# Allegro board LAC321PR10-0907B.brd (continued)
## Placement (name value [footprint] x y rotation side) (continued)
PQ600  AON7934_DFN3X3A-8-10  [AON7934_DFN3X3A8-10]  156.91 125.89 90 top
PQ601  AON7934_DFN3X3A-8-10  [AON7934_DFN3X3A8-10]  162.37 108.98 180 top
PQ800  AON7934_DFN3X3A-8-10  [AON7934_DFN3X3A8-10]  83.33 108 0 top
PQ900  AON7934_DFN3X3A-8-10  [AON7934_DFN3X3A8-10]  82.95 119.18 0 top
PQ1000  AON7934_DFN3X3A-8-10  [AON7934_DFN3X3A8-10]  77.41 100.35 180 top
PR102  100K_0402_1%  [R_0402]  45.21 109.29 90 top
PR103  0_0402_5%  [R_0402]  41.28 127.24 0 top
PR104  1M_0402_5%  [R_0402]  45.21 107.53 90 top
PR105  100K_0402_1%  [R_0402]  49.14 125.44 180 top
PR106  100K_0402_1%  [R_0402]  46.36 124.44 0 top
PR107  100K_0402_1%  [R_0402]  41.32 118.7 90 top
PR108  100K_0402_1%  [R_0402]  51.52 112.49 270 top
PR109  0_0201_1%  [R_0201]  44.75 124.8 0 top
PR110  0_0201_1%  [R_0201]  46.72 129.13 90 top
PR111  100K_0402_1%  [R_0402]  48.26 128.06 90 top
PR112  0_0201_1%  [R_0201]  43.96 128.3 180 top
PR113  0_0201_1%  [R_0201]  46.72 130.88 270 top
PR115  221K_0402_1%  [R_0402]  47.57 139.09 270 top
PR116  100K_0402_1%  [R_0402]  50.68 109.52 90 top
PR117  19.1K_0402_1%  [R_0402]  41.27 140.5 0 top
PR118  0_0402_5%  [R_0402]  42.21 123.35 270 top
PR119  1M_0402_5%  [R_0402]  50.67 107.78 90 top
PR120  100K_0402_1%  [R_0402]  162.36 96.6 270 top
PR121  100_0402_1%  [R_0402]  158.86 95.82 90 top
PR122  100_0402_1%  [R_0402]  159.75 95.82 90 top
PR123  100_0402_1%  [R_0402]  160.59 96.58 0 top
PR124  25.5K_0402_1%  [R_0402]  48.23 126.33 0 top
PR125  25.5K_0402_1%  [R_0402]  49.16 128.99 270 top
PR126  221K_0402_1%  [R_0402]  47.4 135.3 90 top
PR127  100K_0402_1%  [R_0402]  47.28 125.31 180 top
PR128  1.8M_0402_1%  [R_0402]  46.67 137.32 0 top
PR129  100K_0402_1%  [R_0402]  41.33 122.44 90 top
PR130  1.8M_0402_1%  [R_0402]  42.14 135.24 90 top
PR131  0_0402_5%  [R_0402]  42.21 121.36 270 top
PR132  100K_0402_1%  [R_0402]  41.32 120.44 90 top
PR133  100K_0402_1%  [R_0402]  47.68 140.55 180 top
PR134  100K_0402_1%  [R_0402]  44.05 140.54 180 top
PR135  0_0402_5%  [R_0402]  41.31 128.18 0 top
PR136  200K_0402_1%  [R_0402]  42.17 137.84 90 top
PR137  100K_0402_1%  [R_0402]  44.05 133.37 270 top
PR138  100K_0402_1%  [R_0402]  45.83 132.46 90 top
PR139  1M_0402_5%  [R_0402]  42.2 117.85 270 top
PR140  200K_0402_1%  [R_0402]  41.28 134.35 0 top
PR141  1M_0402_5%  [R_0402]  51.52 114.22 270 top
PR142  19.1K_0402_1%  [R_0402]  42.18 132.51 90 top
PR143  0_0402_5%  [R_0402]  48.16 129.88 0 top
PR144  0_0402_5%  [R_0402]  45.88 131.61 0 top
PR145  1K_0402_1%  [R_0402]  51.57 109.52 90 top
PR146  0_0402_5%  [R_0402]  41.27 125.47 0 top
PR147  0_0402_5%  [R_0402]  43.99 131.54 0 top
PR148  0_0402_5%  [R_0402]  41.28 126.35 0 top
PR149  100K_0402_1%  [R_0402]  44.52 85.97 90 top
PR150  0_0402_5%  [R_0402]  26.41 91.24 0 top
PR151  2K_0402_5%  [R_0402]  41.79 85.97 90 top
PR152  0_0402_5%  [R_0402]  26.51 86.67 180 top
PR153  100K_0402_1%  [R_0402]  39.39 91.82 180 top
PR155  100K_0402_1%  [R_0402]  34.18 71.56 90 top
PR156  0_0201_1%  [R_0201]  46.93 139.8 0 top
PR157  100K_0402_1%  [R_0402]  42.2 91.96 90 top
PR158  100K_0402_1%  [R_0402]  43.08 92.86 270 top
PR159  0_0402_5%  [R_0402]  41.07 96.79 90 top
PR160  0_0402_5%  [R_0402]  40.42 92.87 270 top
PR161  0_0402_5%  [R_0402]  160.59 95.69 0 top
PR162  100K_0402_1%  [R_0402]  41.31 92.87 270 top
PR165  0_0805_5%  [R_0805]  83.42 87.84 90 top
PR166  0_0805_5%  [R_0805]  81.69 87.84 90 top
PR167  0_0805_5%  [R_0805]  79.98 87.84 90 top
PR200  1M_0402_5%  [R_0402]  51.3 135.81 180 top
PR201  100K_0402_1%  [R_0402]  66.27 140.98 90 top
PR202  100K_0402_1%  [R_0402]  53.88 148.68 270 top
PR203  100K_0402_1%  [R_0402]  66.2 137.07 0 top
PR204  1M_0402_5%  [R_0402]  49.54 135.81 180 top
PR205  1M_0402_5%  [R_0402]  64.37 141.85 0 top
PR206  1M_0402_5%  [R_0402]  76.38 119.79 180 top
PR207  100K_0402_1%  [R_0402]  61.73 139.63 90 top
PR208  100K_0402_1%  [R_0402]  60.7 138.59 180 top
PR209  1.8M_0402_1%  [R_0402]  80.12 129.19 270 top
PR210  100K_0402_1%  [R_0402]  61.32 148.57 0 top
PR211  115K_0402_1%  [R_0402]  74.5 128.38 90 top
PR212  430K_0402_5%  [R_0402]  73.62 128.38 90 top
PR213  249K_0402_1%  [R_0402]  78.23 129.18 180 top
PR214  0_0402_5%  [R_0402]  62.22 147.7 270 top
PR215  1M_0402_5%  [R_0402]  61.58 137.88 90 top
PR216  1M_0402_5%  [R_0402]  60.68 136.19 90 top
PR217  422K_0402_1%  [R_0402]  76.43 128.32 180 top
PR218  165K_0402_1%  [R_0402]  65.31 120.33 0 top
PR219  100K_0402_1%  [R_0402]  66.22 119.44 180 top
PR220  78.7K_0402_1%  [R_0402]  68.15 129.33 180 top
PR221  15.4K_0402_1%  [R_0402]  67.37 128.23 0 top
PR222  49.9K_0402_1%  [R_0402]  68.28 127.35 180 top
PR223  2K_0402_5%  [R_0402]  55.92 148.69 270 top
PR224  100K_0402_1%  [R_0402]  53 147.76 90 top
PR225  100K_0402_1%  [R_0402]  72.57 122.97 180 top
PR226  0_0402_5%  [R_0402]  70.75 122.97 180 top
PR227  100K_0402_1%  [R_0402]  72.88 124.04 90 top
PR228  0_0402_5%  [R_0402]  77.63 123.6 0 top
PR229  2M_0402_5%  [R_0402]  66.34 123.07 0 top
PR230  2M_0402_5%  [R_0402]  70.14 128.02 0 top
PR231  0_0402_5%  [R_0402]  54.81 148.67 270 top
PR232  0_0402_5%  [R_0402]  56.81 148.69 270 top
PR233  0_0201_1%  [R_0201]  50.89 143.34 90 top
PR234  0_0201_1%  [R_0201]  49.74 143.34 90 top
PR235  0_0201_1%  [R_0201]  51.64 143.34 90 top
PR236  0_0201_1%  [R_0201]  50.33 143.34 90 top
PR237  560K_0402_5%  [R_0402]  59.21 146.24 0 top
PR238  0_0201_1%  [R_0201]  61.36 143.81 270 top
PR239  0_0201_1%  [R_0201]  69.55 129.32 180 top
PR240  0_0402_5%  [R_0402]  72.12 128.15 90 top
PR241  560K_0402_5%  [R_0402]  74.33 122.77 90 top
PR242  0_0402_5%  [R_0402]  70.31 129.07 0 top
PR243  0_0402_5%  [R_0402]  65.31 123.24 90 top
PR244  100K_0402_1%  [R_0402]  60.85 140.55 270 top
PR245  560K_0402_5%  [R_0402]  74.48 120.05 180 top
PR246  100K_0402_1%  [R_0402]  61.63 134.24 270 top
PR247  560K_0402_5%  [R_0402]  62.28 143.6 270 top
PR248  0_0402_5%  [R_0402]  73.64 121.9 270 top
PR249  100K_0402_1%  [R_0402]  75.47 120.68 0 top
PR250  0_0402_5%  [R_0402]  173.16 109.32 0 top
PR251  20K_0402_1%  [R_0402]  59.98 142.25 180 top
PR252  100K_0201_1%  [R_0201]  89.66 93.57 90 top
PR253  100K_0201_1%  [R_0201]  90.23 93.57 90 top
PR254  165K_0402_1%  [R_0402]  65.42 117.64 90 top
PR255  100K_0402_1%  [R_0402]  50.74 141.61 180 top
PR256  78.7K_0402_1%  [R_0402]  65.31 129.32 0 top
PR257  0_0402_5%  [R_0402]  94.62 94.46 90 top
PR258  100K_0402_1%  [R_0402]  93.71 96.22 90 top
PR259  0_0402_5%  [R_0402]  68.35 119.13 180 top
PR300  1M_0402_5%  [R_0402]  168.24 109.32 0 top
PR301  1M_0402_5%  [R_0402]  168.74 108.36 180 top
PR302  100K_0402_5%  [R_0402]  171.91 107.6 180 top
PR303  100K_0402_5%  [R_0402]  171.91 106.71 180 top
PR304  820K_0402_1%  [R_0402]  169.63 104.94 180 top
PR305  0_0201_1%  [R_0201]  166.63 109.14 90 top
PR306  0_0201_1%  [R_0201]  167.2 109.72 270 top
PR307  0_0201_1%  [R_0201]  170.02 108.24 180 top
PR400  0.01_1206_1%  [R_1206_4P-D]  43.07 117.86 0 top
PR401  0_0402_5%  [R_0402]  57.82 134.22 270 top
PR402  0_0402_5%  [R_0402]  58.71 134.22 270 top
PR403  10_1206_5%  [R_1206]  60.17 134.77 270 top
PR404  200K_0402_1%  [R_0402]  50.97 134.22 270 top
PR405  49.9K_0402_1%  [R_0402]  51.86 133.31 90 top
PR406  2.2_0603_5%  [R_0603]  59.35 128.3 0 top
PR407  0_0402_5%  [R_0402]  50.2 127.03 0 top
PR408  0_0402_5%  [R_0402]  50.2 126.14 0 top
PR409  100K_0402_1%  [R_0402]  53.64 134.22 270 top
PR410  0.01_1206_1%  [R_1206_4P-D]  66.44 88.04 0 top
PR411  0_0402_5%  [R_0402]  52.75 134.22 270 top
PR412  0_0402_5%  [R_0402]  50.08 134.22 270 top
PR413  2_1206_5%  [R_1206]  60.18 110.4 90 top
PR414  154K_0402_1%  [R_0402]  53.75 132.37 0 top
PR415  0_0402_5%  [R_0402]  50.2 131.48 0 top
PR416  75_0402_1%  [R_0402]  50.2 127.92 0 top
PR417  0_0402_5%  [R_0402]  50.2 128.81 0 top
PR418  10K_0402_1%  [R_0402]  59.29 125.76 0 top
PR419  20K_0402_1%  [R_0402]  51.11 129.7 180 top
PR420  4.02K_0402_1%  [R_0402]  54.84 124.32 270 top
PR421  1K_0402_1%  [R_0402]  50.12 121.7 90 top
PR422  10_0603_1%  [R_0603]  52.43 124.56 270 top
PR423  0_0402_5%  [R_0402]  50.2 125.26 0 top
PR424  0_0402_5%  [R_0402]  56.75 122.97 0 top
PR425  121K_0402_1%  [R_0402]  51.11 123.48 180 top
PR426  0_0402_5%  [R_0402]  50.2 124.37 0 top
PR427  4.02K_0402_1%  [R_0402]  54.53 134.22 270 top
PR428  560K_0402_5%  [R_0402]  52.14 139.52 270 top
PR500  0_0402_5%  [R_0402]  164.06 116.06 270 top
PR501  0_0402_5%  [R_0402]  174.02 123.73 0 top
PR502  0_0402_5%  [R_0402]  161.02 119.03 90 top
PR503  4.7_0805_5%  [R_0805]  159.2 118.4 180 top
PR504  4.7_0805_5%  [R_0805]  178.09 123.86 90 top
PR505  100_0201_1%  [R_0201]  160.25 120.81 90 top
PR506  430K_0402_5%  [R_0402]  159.94 123.03 90 top
PR507  100_0201_1%  [R_0201]  162.79 123.64 270 top
PR508  0_0402_5%  [R_0402]  161.19 123.22 0 top
PR509  0_0402_5%  [R_0402]  159.04 122.18 0 top
PR510  0_0402_5%  [R_0402]  176.08 130.72 180 top
PR511  0_0402_5%  [R_0402]  166.1 128.56 180 top
PR512  0_0402_5%  [R_0402]  185.4 133.82 90 top
PR513  4.7_0805_5%  [R_0805]  164.19 134.5 90 top
PR514  4.7_0805_5%  [R_0805]  179.56 129.7 270 top
PR515  120K_0402_1%  [R_0402]  167.11 127.92 90 top
PR516  0_0402_5%  [R_0402]  176.6 118.26 90 top
PR517  0_0402_5%  [R_0402]  178.47 118.41 90 top
PR518  0_0402_5%  [R_0402]  172.6 115.62 270 top
PR519  4.7_0805_5%  [R_0805]  186.96 116.49 0 top
PR520  71.5K_0402_1%  [R_0402]  175.72 119.93 270 top
PR600  0_0402_5%  [R_0402]  171.81 118.91 0 top
PR601  0_0402_5%  [R_0402]  170.54 128.76 270 top
PR602  4.7_0805_5%  [R_0805]  172.57 131.99 180 top
PR603  4.7_0805_5%  [R_0805]  171.32 116.76 270 top
PR604  0_0201_5%  [R0201_0OHM]  173.34 112.99 90 top
PR605  0_0402_5%  [R_0402]  161.44 125.38 0 top
PR606  0_0402_5%  [R_0402]  158.02 124.75 270 top
PR607  4.7_0805_5%  [R_0805]  152.17 128.23 90 top
PR608  150K_0402_1%  [R_0402]  161.45 129.83 0 top
PR609  0_0402_5%  [R_0402]  164.45 106.51 90 top
PR610  0_0402_5%  [R_0402]  163.56 105.57 0 top
PR611  4.7_0805_5%  [R_0805]  158.73 104.68 0 top
PR612  0_0201_5%  [R0201_0OHM]  151.66 105.06 180 bottom
PR613  360K_0402_1%  [R_0402]  165.97 117.56 270 top
PR700  10K_0402_1%  [R_0402]  178.3 121.28 0 top
PR703  0_0201_1%  [R_0201]  172.45 108.91 270 top
PR704  0_0201_1%  [R_0201]  176.6 109.47 180 top
PR709  2K_0402_5%  [R_0402]  165.08 119.3 270 top
PR710  2K_0402_5%  [R_0402]  166.11 119.5 270 top
PR711  150_0402_1%  [R_0402]  173.97 121.93 90 top
PR712  0_0201_1%  [R_0201]  164.2 112.75 90 top
PR713  0_0201_1%  [R_0201]  165.5 112.72 90 top
PR714  10K_0402_1%  [R_0402]  185.11 120.23 270 top
PR715  75_0402_1%  [R_0402]  186 120.23 270 top
PR717  80.6K_0402_1%  [R_0402]  173.59 118.19 90 top
PR718  0_0201_1%  [R_0201]  163.15 127.03 180 top
PR719  0_0402_5%  [R_0402]  173.45 116.9 0 top
PR733  0_0201_1%  [R_0201]  172.83 111.01 270 top
PR734  0_0201_1%  [R_0201]  173.4 111.01 270 top
PR735  0_0201_1%  [R_0201]  174.81 109.47 0 top
PR736  0_0201_1%  [R_0201]  174.64 124.49 180 top
PR737  0_0201_1%  [R_0201]  177.65 108.24 90 top
PR738  0_0201_1%  [R_0201]  161.94 127.03 180 top
PR739  499_0201_1%  [R_0201]  174.19 125.13 0 top
PR740  1.4K_0201_1%  [R_0201]  173.46 125.17 270 top
PR741  24.9K_0402_1%  [R_0402]  183.62 135.34 90 top
PR742  20K_0201_5%  [R_0201]  157.55 130.46 0 top
PR745  47K_0402_1%_NCP15WB473F03RC  [R_0402]  183.6 137.12 0 top
PR746  0_0201_1%  [R_0201]  185.82 118.14 0 top
PR747  0_0201_1%  [R_0201]  185.22 118.14 180 top
PR800  75_0402_1%  [R_0402]  67.11 112.68 180 top
PR801  100K_0402_1%  [R_0402]  75.67 104.54 90 top
PR802  100_0402_1%  [R_0402]  68.1 110.02 0 top
PR803  45.3_0402_1%  [R_0402]  68.1 112.68 0 top
PR804  0_0402_5%  [R_0402]  73.01 106.38 90 top
PR805  0_0402_5%  [R_0402]  82.92 103.89 180 top
PR806  0_0402_5%  [R_0402]  86.34 106.15 270 top
PR807  4.7_0805_5%  [R_0805]  88.72 112.68 180 top
PR808  680_0402_1%  [R_0402]  90.6 112.16 90 top
PR809  680_0402_1%  [R_0402]  90.58 113.95 0 top
PR810  2.4K_0402_1%  [R_0402]  75.6 112.05 0 top
PR811  2.4K_0402_1%  [R_0402]  89.71 112.16 90 top
PR812  0_0402_5%  [R_0402]  66.2 110.9 0 top
PR813  1M_0402_5%  [R_0402]  66.2 110.02 0 top
PR814  2.4K_0402_1%  [R_0402]  75.6 112.94 0 top
PR815  0_0402_5%  [R_0402]  66.21 108.22 90 top
PR816  47_0402_1%  [R_0402]  68.1 107.35 0 top
PR817  47_0402_1%  [R_0402]  79.8 114.79 270 top
PR818  100K_0402_1%  [R_0402]  65.3 113.39 270 top
PR819  84.5K_0402_1%  [R_0402]  66.26 101.57 0 top
PR820  84.5K_0402_1%  [R_0402]  66.26 100.68 0 top
PR821  2K_0402_5%  [R_0402]  76.08 116.58 0 top
PR822  1.6K_0402_1%  [R_0402]  77.87 116.59 270 top
PR823  4.3K_0402_1%  [R_0402]  78.91 113.88 90 top
PR824  33K_0402_1%  [R_0402]  78.02 114.79 270 top
PR825  100K_0402_1%  [R_0402]  65.31 106.72 90 top
PR826  0_0402_5%  [R_0402]  75.23 113.88 90 top
PR827  0_0402_5%  [R_0402]  74.34 113.88 90 top
PR828  33K_0402_1%  [R_0402]  75.23 115.91 90 top
PR829  100K_0402_1%  [R_0402]  162.36 124.37 180 top
PR830  51K_0402_1%  [R_0402]  66.15 115.31 90 top
PR831  0_0402_5%  [R_0402]  66.29 117.08 0 top
PR832  0_0402_5%  [R_0402]  74.78 107.3 270 top
PR833  200K_0402_1%  [R_0402]  75.67 107.3 270 top
PR834  200K_0402_1%  [R_0402]  76.55 107.3 270 top
PR835  49.9_0402_1%  [R_0402]  68.1 113.57 0 top
PR836  10_0402_1%  [R_0402]  68.1 110.9 0 top
PR837  75_0402_1%  [R_0402]  67.11 111.79 180 top
PR838  0_0402_5%  [R_0402]  69.02 111.79 180 top
PR839  0_0805_5%  [R_0805]  71.41 100.6 0 top
PR840  0_0805_5%  [R_0805]  71.41 98.88 0 top
PR841  0_0805_5%  [R_0805]  71.41 102.33 0 top
PR900  0_0402_5%  [R_0402]  83.37 113.95 180 top
PR901  0_0402_5%  [R_0402]  85.71 116.54 90 top
PR902  4.7_0805_5%  [R_0805]  87.67 124.62 180 top
PR903  680_0402_1%  [R_0402]  90.18 123.3 90 top
PR904  680_0402_1%  [R_0402]  90.13 125.1 0 top
PR905  2.7K_0402_1%  [R_0402]  70.78 113.88 90 top
PR906  2.4K_0402_1%  [R_0402]  89.26 123.3 90 top
PR907  2.7K_0402_1%  [R_0402]  69.89 113.88 90 top
PR908  2K_0402_5%  [R_0402]  74.34 115.91 90 top
PR909  1.6K_0402_1%  [R_0402]  74.35 117.7 180 top
PR910  4.3K_0402_1%  [R_0402]  74.35 118.59 180 top
PR911  22K_0402_1%  [R_0402]  72.57 117.7 180 top
PR913  0_0402_5%  [R_0402]  72.56 113.88 90 top
PR914  0_0402_5%  [R_0402]  73.45 113.88 90 top
PR915  33K_0402_1%  [R_0402]  67.11 113.57 180 top
PR917  2K_0402_5%  [R_0402]  68.05 115.31 90 top
PR918  51K_0402_1%  [R_0402]  68.04 117.08 0 top
PR919  0_0402_5%  [R_0402]  69.02 114.46 180 top
PR920  200K_0402_1%  [R_0402]  70.78 116.67 90 top
PR921  200K_0402_1%  [R_0402]  69.89 116.67 90 top
PR1000  0_0402_5%  [R_0402]  78.28 103.79 0 top
PR1001  4.7_0805_5%  [R_0805]  81.43 102.14 0 top
PR1002  680_0402_1%  [R_0402]  81.21 94.78 180 top
PR1003  680_0402_1%  [R_0402]  79.42 94.79 270 top
PR1004  0_0402_5%  [R_0402]  77.58 95.59 90 top
PR1005  4.7K_0402_1%  [R_0402]  78.53 93.87 90 top
PR1006  5.1K_0402_1%  [R_0402]  69.01 106.47 270 top
PR1007  5.1K_0402_1%  [R_0402]  68.12 106.47 270 top
PR1008  560_0402_1%  [R_0402]  66.22 105.51 180 top
PR1009  5.6K_0402_1%  [R_0402]  65.31 104.62 0 top
PR1010  4.3K_0402_1%  [R_0402]  68.1 102.9 0 top
PR1011  10K_0402_1%  [R_0402]  66.22 103.73 180 top
PR1012  47K_0402_1%  [R_0402]  69.96 107.3 270 top
PR1013  75K_0402_1%  [R_0402]  68.01 100.27 0 top
PR1014  5.6K_0402_1%  [R_0402]  69.02 102.01 180 top
PR1015  0_0402_5%  [R_0402]  74.78 105.46 270 top
PR1016  0_0402_5%  [R_0402]  70.85 107.3 270 top
PR1017  0_0402_5%  [R_0402]  73.01 105.52 270 top
PR1018  100K_0402_1%  [R_0402]  73.89 107.3 270 top
PR1019  0_0402_5%  [R_0402]  69.96 105.52 270 top
PR1020  30K_0402_1%  [R_0402]  65.39 101.58 270 top
PR1021  30K_0402_1%  [R_0402]  66.2 114.46 0 top
PR1022  30K_0402_1%  [R_0402]  76.13 117.7 180 top
PR1024  0_0402_5%  [R_0402]  66.2 106.4 0 top
PR1025  62K_0402_1%  [R_0402]  70.85 105.52 270 top
PR1026  20K_0402_1%  [R_0402]  71.99 105.39 270 top
PR1027  0_0402_5%  [R_0402]  73.89 105.46 270 top
PR1028  0_0402_5%  [R_0402]  66.2 107.29 0 top
PR1029  0_0402_5%  [R_0402]  69.95 103.73 0 top
PU100  -  [TLV1702AIDGKR_VSSOP8]  45.29 139.12 180 top
PU101  -  [SN74AHC1G08DCKR_SC70-5]  41.49 129.32 0 top
PU102  -  [RT9069-33GB_SOT23-5]  30.59 67.85 0 top
PU200  -  [RT9069-33GB_SOT23-5]  48.68 138.83 270 top
PU201  SN74LVC1G02DCKR_SC70-5  [P_SN74LVC1G02DCKR_SC70_5P]  63.76 139.25 270 top
PU202  -  [RT9069-33GB_SOT23-5]  93.2 95.12 180 top
PU203  SN74LVC1G02DCKR_SC70-5  [P_SN74LVC1G02DCKR_SC70_5P]  59.85 144.25 180 top
PU204  -  [SN74AHC1G08DCKR_SC70-5]  62.84 134.92 270 top
PU205  SN74LVC1G02DCKR_SC70-5  [P_SN74LVC1G02DCKR_SC70_5P]  63.73 136.81 270 top
PU206  -  [LM393DMR2G_MICRO8]  71.67 124.23 90 top
PU207  -  [LM393DMR2G_MICRO8]  74.09 127.02 270 top
PU208  -  [OPA376AIDCKR_SC70-5]  67.28 120.19 0 top
PU209  SN74LVC1G02DCKR_SC70-5  [P_SN74LVC1G02DCKR_SC70_5P]  71.56 121.32 90 top
PU300  -  [SN74LVC1G123DCUR_VSSOP8]  169.73 105.9 90 top
PU400  BQ24777RUYR_WQFN28_4x4  [BQ24777RUYR_WQFN28_4X4]  56.17 130.61 270 top
PU500  -  [BD99992GW-E2_UCSP55M5C195]  165.59 126.4 0 top
PU800  -  [BD99991GW-E2_UCSP55M4C99]  74.02 112.35 270 top
PU801  -  [BD9515NUX-E2_VSON008X2020-8]  83.94 104.09 0 top
PU901  -  [BD9515NUX-E2_VSON008X2020-8]  83.29 115.22 0 top
Q10  -  [DMN2400UV-7_SOT-563-6]  144.5 124.28 270 top
Q25  DII-DMN65D8LW-7  [SSM3K7002FU_SC70-3]  227.56 116.69 0 top
Q27  -  [MMBT3904WH_SOT323-3]  115.31 126.14 270 top
Q28  -  [MMBT3904WH_SOT323-3]  18.14 17.14 180 top
Q29  -  [MMBT3904WH_SOT323-3]  92.81 123.31 180 top
Q30  -  [MMBT3904WH_SOT323-3]  224.29 119.54 0 top
Q31  -  [MMBT3904WH_SOT323-3]  38.12 108.94 270 top
Q43  DII-DMN65D8LW-7  [SSM3K7002FU_SC70-3]  31.35 95.6 0 top
Q68  DII-DMN65D8LW-7  [SSM3K7002FU_SC70-3]  17.63 10.11 0 top
Q86  -  [DMN66D0LDW-7_SOT363-6]  17.25 94.33 90 top
Q89  -  [DMN66D0LDW-7_SOT363-6]  25.15 96.02 270 top
Q330  -  [DMP3099L-7_SOT23-3]  220.53 119.82 0 top
Q340  DII-DMN65D8LW-7  [SSM3K7002FU_SC70-3]  227.03 136.5 270 top
Q341  -  [PMDXB600UNE_DFN1010B-6]  246.75 138.62 180 top
Q342  -  [PMDXB600UNE_DFN1010B-6]  216.18 138.11 90 top
Q343  S TR 2N7002KW 1N SOT323-3  [SSM3K7002FU_SC70-3]  202.71 142.48 0 top
Q344  -  [DMP3099L-7_SOT23-3]  199.55 145.98 180 top
Q345  -  [DMN66D0LDW-7_SOT363-6]  56.8 142.06 0 top
Q346  -  [DMN66D0LDW-7_SOT363-6]  181 101.97 0 top
Q347  -  [DMN66D0LDW-7_SOT363-6]  220.21 117.99 270 top
Q348  -  [DMN66D0LDW-7_SOT363-6]  219.19 116.69 90 top
Q349  -  [DMN66D0LDW-7_SOT363-6]  204.05 127.54 0 top
QA1  -  [DMN66D0LDW-7_SOT363-6]  19.09 13.25 90 top
QR1  DII-DMN65D8LW-7~D  [SSM3K7002FU_SC70-3]  29.33 72.93 270 top
QT18  -  [DMN2400UFB4-7_DFN1006H4-3]  231.06 106.42 180 top
QT19  -  [PMDXB600UNE_DFN1010B-6]  6.21 56.71 270 top
QT20  -  [PMDXB600UNE_DFN1010B-6]  128.65 81.12 270 top
QT21  -  [PMDXB600UNE_DFN1010B-6]  127.99 83.83 180 top
R1  1M_0201_1%  [R_0201]  143.71 123.4 180 top
R2  240_0201_1%  [R_0201]  114.15 116.33 90 top
R3  240_0201_1%  [R_0201]  102.85 109.63 0 top
R4  240_0201_1%  [R_0201]  123.3 125.6 90 top
R5  240_0201_1%  [R_0201]  127.91 116.87 180 top
R6  8.2K_0201_1%  [R_0201]  107.55 125.17 270 top
R7  8.2K_0201_1%  [R_0201]  122.66 123.82 90 top
R8  10_0201_1%  [R_0201]  106.91 125.17 270 top
R9  4.99_0402_1%  [R_0402]  106.84 110.52 0 top
R10  8.2K_0201_1%  [R_0201]  108.18 124.58 90 top
R11  8.2K_0201_1%  [R_0201]  123.3 124.4 270 top
R12  24.9_0201_1%  [R_0201]  105.39 124.58 90 top
R13  24.9_0201_1%  [R_0201]  105.05 109.63 180 top
R14  8.2K_0201_1%  [R_0201]  121.35 127.15 90 top
R15  10_0201_1%  [R_0201]  120.64 128.95 0 top
R16  8.2K_0201_1%  [R_0201]  121.37 128.34 180 top
R17  24.9_0201_1%  [R_0201]  120.78 127.73 270 top
R18  100K_0402_5%~D  [R_0402]  246.74 135.89 90 top
R19  100K_0402_5%~D  [R_0402]  246.81 140.61 270 top
R21  100K_0402_5%~D  [R_0402]  214.1 138.92 270 top
R22  100K_0402_5%~D  [R_0402]  218.12 138.21 180 top
R24  0.01_0603_1%  [R_0603]  171.75 99.73 0 top
R25  220K_0201_5%  [R_0201]  172.83 104.47 270 top
R29  220K_0201_5%  [R_0201]  186.76 100.49 0 top
R30  1K_0603_1%  [R_0603]  185.24 104.49 270 top
R31  220K_0201_5%  [R_0201]  177.31 99.73 180 top
R32  220K_0201_5%  [R_0201]  179 100.44 270 top
R33  10K_0402_5%  [R_0402]  20.78 18.32 180 top
R34  0_0201_5%  [R0201_0OHM]  66.12 149.42 0 top
R35  0_0402_5%  [R_0402]  238.16 116.57 0 top
R36  0_0201_5%  [R0201_0OHM]  66.12 148.85 0 top
R37  0_0402_5%  [R_0402]  238.16 117.58 0 top
R38  0_0201_5%  [R0201_0OHM]  66.14 144.79 90 top
R39  0_0201_5%  [R0201_0OHM]  65.55 144.79 90 top
R40  0_0402_5%~D  [R0402_0OHM]  242.41 121.47 90 top
R41  100K_0201_5%  [R_0201]  242.97 128.98 180 top
R42  220K_0201_5%  [R_0201]  241.8 123.15 90 top
R43  220K_0201_5%  [R_0201]  222.83 123.45 0 top
R44  0_0402_5%  [R_0402]  37.71 104.3 180 top
R45  0_0402_5%  [R_0402]  37.71 103.28 180 top
R46  10K_0201_1%  [R_0201]  14.48 96.06 270 top
R47  10K_0201_1%  [R_0201]  29.86 97.47 90 top
R48  47K_0402_5%  [R_0402]  34.65 97.19 90 top
R49  0_0402_5%  [R_0402]  33.13 97.19 90 top
R50  0_0201_5%  [R0201_0OHM]  35.41 98.07 270 top
R51  100K_0402_5%  [R_0402]  19.07 94.5 180 top
R52  10K_0201_1%  [R_0201]  30.85 94.57 180 top
R53  0_0402_5%~D  [R0402_0OHM]  19.07 95.39 180 top
R54  0_0402_5%  [R_0402]  26.47 97.94 0 top
R55  0_0201_5%  [R0201_0OHM]  24.87 101.96 270 bottom
R56  0_0402_5%~D  [R0402_0OHM]  29.13 96.5 180 top
R57  0_0201_5%  [R0201_0OHM]  24.24 101.96 270 bottom
R58  0_0201_5%  [R0201_0OHM]  23.6 101.96 270 bottom
R59  0_0402_5%  [R_0402]  196.15 105.7 180 top
R60  10K_0201_5%  [R_0201]  203.9 136.81 0 top
R61  10K_0201_1%  [R_0201]  23.7 96.05 0 top
R62  100K_0201_5%  [R_0201]  201.7 146.92 180 top
R63  0_0402_5%~D  [R_0402]  197.11 144.99 270 top
R64  0_0201_5%  [R_0201]  14.71 100.74 270 top
R65  1M_0402_5%  [R_0402]  197.08 141.47 270 top
R66  0_0402_5%~D  [R0402_0OHM]  202.41 146.43 0 top
R67  1M_0402_5%  [R_0402]  56.24 86.47 270 top
R68  0_0402_5%  [R_0402]  129.27 89.3 180 top
R69  8.2K_0201_5%  [R_0201]  196.87 139.37 270 top
R70  BLM15HD601SN1D  [MURAT_BLM15HG601SN1D_2P]  189.58 137.56 90 top
R71  BLM15HD601SN1D  [MURAT_BLM15HG601SN1D_2P]  190.72 137.56 90 top
R72  0_0402_5%~D  [R_0402]  192.25 143.65 0 bottom
R73  100K_0201_5%  [R_0201]  194.81 142.83 180 bottom
R74  8.2K_0201_5%  [R_0201]  195.42 139.29 270 top
R75  0.01_0603_1%  [R_0603]  196.81 146.35 90 top
R76  0.01_0603_1%  [R_0603]  191.94 140.62 180 top
R77  0.01_0603_1%  [R_0603]  191.94 143.16 180 top
R78  1M_0402_5%  [R_0402]  6 46.55 90 top
R79  0_0402_5%~D  [R_0402]  197.96 141.35 90 top
R80  0_0402_5%~D  [R_0402]  159.23 137.07 180 top
R81  0.01_0603_1%  [R_0603]  193.34 148.5 180 top
R82  0_0402_5%  [R_0402]  129.27 88.28 180 top
R83  10K_0201_5%  [R_0201]  66.12 148.28 0 top
R84  10K_0201_5%  [R_0201]  66.14 147.12 0 top
R85  10K_0201_5%  [R_0201]  66.14 145.97 0 top
R86  0_0402_5%  [R_0402]  116.95 125.43 90 top
R87  0_0402_5%  [R_0402]  117.96 125.43 90 top
R88  0_0402_5%~D  [R0402_0OHM]  119.86 125.12 90 top
R89  0_0402_5%~D  [R0402_0OHM]  118.84 125.12 90 top
R90  1K_0402_1%  [R_0402]  120.78 94.45 90 top
R91  100K_0201_5%  [R_0201]  217.4 105.98 0 top
R92  0_0402_5%~D  [R_0402]  202.89 148.5 180 top
R93  0_0402_5%~D  [R_0402]  14.46 32.49 270 top
R94  0_0402_5%~D  [R_0402]  13.44 32.49 270 top
R95  0_0402_5%~D  [R_0402]  15.04 16.29 180 top
R100  0_0402_5%  [R_0402]  19.08 98.53 90 top
R101  0_0402_5%  [R_0402]  18.07 98.53 90 top
R102  0_0402_5%  [R_0402]  37.71 102.4 180 top
R103  10K_0201_5%  [R_0201]  217.4 108.34 0 top
R104  10K_0201_5%  [R_0201]  217.4 106.6 0 top
R105  0_0402_5%  [R_0402]  37.71 101.38 180 top
R106  1M_0402_5%  [R_0402]  50.27 86.55 270 top
R107  0_0402_5%  [R_0402]  207.88 108.57 90 top
R108  100K_0201_5%  [R_0201]  201.7 147.51 180 top
R109  10K_0201_5%  [R_0201]  217.99 107.75 180 top
R110  10K_0201_5%  [R_0201]  217.99 107.17 180 top
R111  100K_0201_5%  [R_0201]  192.35 142.91 0 bottom
R112  0_0201_5%  [R_0201]  230.22 111.13 0 top
R115  0.01_0603_1%  [R_0603]  195.73 147.99 180 top
R116  0.01_0603_1%  [R_0603]  191.94 141.89 180 top
R117  0.01_0603_1%  [R_0603]  192.77 139.42 270 top
R118  0.01_0603_1%  [R_0603]  86.66 129.19 180 top
R119  0_0402_5%  [R_0402]  47.12 90.76 180 top
R120  0_0402_5%  [R_0402]  47.12 91.65 180 top
R121  0_0402_5%~D  [R_0402]  15.04 17.31 180 top
R124  0_0402_5%~D  [R_0402]  233.28 110.68 270 top
R125  0_0402_5%~D  [R_0402]  232.26 110.68 270 top
R126  100K_0201_5%  [R_0201]  48.56 89.35 270 top
R127  100K_0201_5%  [R_0201]  48.57 90.68 180 top
R129  100K_0201_5%  [R_0201]  47.48 89.35 270 top
R130  47K_0201_5%  [R_0201]  80.75 133.35 90 top
R133  0_0402_5%  [R_0402]  98.71 89.06 0 top
R134  0_0402_5%~D  [R0402_0OHM]  100.59 89.97 270 top
R135  0_0402_5%~D  [R0402_0OHM]  192.89 99.53 90 top
R136  0_0402_5%  [R_0402]  192 99.53 90 top
R137  100K_0201_5%  [R_0201]  48.57 91.75 180 top
R138  0_0402_5%  [R_0402]  117.29 88.48 90 top
R142  0_0402_5%  [R_0402]  127.67 80.54 90 top
R143  0_0402_5%  [R_0402]  125.88 82.73 90 top
R155  4.3K_0402_5%  [R_0402]  232.64 131.43 270 top
R156  0_0402_5%~D  [R0402_0OHM]  237.8 130.08 180 top
R157  0_0402_5%  [R_0402]  235.87 128.56 0 top
R160  0_0402_5%~D  [R0402_0OHM]  237.33 122.26 0 top
R161  100K_0201_5%  [R_0201]  231.48 123.06 270 bottom
R162  100K_0201_5%  [R_0201]  237.84 120.09 180 top
R164  0_0402_5%~D  [R0402_0OHM]  227.21 124.54 0 top
R165  0_0402_5%  [R_0402]  230.54 117.38 0 top
R166  0_0402_5%~D  [R0402_0OHM]  230.54 116.49 0 top
R167  10K_0201_5%  [R_0201]  229.85 128.39 90 top
R168  2.2K_0201_5%  [R_0201]  237.34 123.36 0 top
R169  2.2K_0201_5%  [R_0201]  233.51 123.06 270 bottom
R170  100K_0201_5%  [R_0201]  230.84 122.47 90 bottom
R171  10K_0201_5%  [R_0201]  230.55 118.49 90 top
R172  43_0201_5%  [R_0201]  237.26 120.72 0 top
R173  10K_0201_5%  [R_0201]  233.53 116.45 90 bottom
R174  10K_0201_5%  [R_0201]  229.98 119.07 270 top
R175  1K_0201_5%  [R_0201]  236.25 132.56 270 top
R176  0_0402_5%~D  [R0402_0OHM]  233.53 131.43 270 top
R177  10K_0201_5%  [R_0201]  9.42 56.99 180 top
R178  100K_0201_5%  [R_0201]  239.63 119.06 90 top
R179  0_0402_5%~D  [R0402_0OHM]  232.38 115.6 0 top
R180  10_0402_1%  [R_0402]  228.12 123.66 180 top
R181  SHORT PADS  [SHORTPADS]  240.57 118.85 270 top
R182  0_0402_5%  [R_0402]  237.66 132.2 0 top
R183  4.7K_0201_5%  [R_0201]  61.36 94.47 180 top
R184  0_0402_5%~D  [R0402_0OHM]  233.58 128.43 90 top
R185  4.7K_0201_5%  [R_0201]  61.36 93.2 180 top
R186  4.7K_0201_5%  [R_0201]  61.36 93.84 180 top
R187  4.7K_0201_5%  [R_0201]  61.36 90.66 180 top
R188  4.7K_0201_5%  [R_0201]  61.36 91.3 180 top
R189  4.7K_0201_5%  [R_0201]  61.36 92.57 180 top
R190  4.7K_0201_5%  [R_0201]  61.36 91.93 180 top
R191  4.7K_0201_5%  [R_0201]  61.36 89.39 180 top
R192  49.9_0402_1%  [R_0402]  212.34 143.99 90 top
R193  1.5K_0201_1%  [R_0201]  235.44 117.67 270 top
R194  4.7K_0201_5%  [R_0201]  61.36 90.03 180 top
R195  10K_0201_5%  [R_0201]  208.12 144.29 90 top
R196  4.7K_0201_5%  [R_0201]  55.99 94.52 90 bottom
R197  4.7K_0201_5%  [R_0201]  54.84 94.52 90 bottom
R198  4.7K_0201_5%  [R_0201]  61.36 95.11 180 top
R199  4.7K_0201_5%  [R_0201]  58.53 96.46 270 top
R200  0.01_0603_1%  [R_0603]  192.64 135.1 90 top
R201  0.01_0603_1%  [R_0603]  193.91 136.5 270 top
R202  0.01_0603_1%  [R_0603]  139.08 124 0 top
R203  4.7K_0201_5%  [R_0201]  59.16 96.46 270 top
R204  0.01_0603_1%  [R_0603]  193.27 132.69 90 top
R205  0.01_0603_1%  [R_0603]  238.03 134.13 0 top
R206  0.01_0603_1%  [R_0603]  198.43 124.19 270 top
R207  100K_0201_5%  [R_0201]  232.84 134.73 0 top
R208  100K_0201_5%  [R_0201]  194.29 127.25 90 top
R209  100K_0201_5%  [R_0201]  233.36 136.88 270 top
R210  4.7K_0201_5%  [R_0201]  21.14 47.32 180 bottom
R211  0.01_0603_1%  [R_0603]  38.33 86.52 0 top
R212  0.01_0603_1%  [R_0603]  238.02 137.19 0 top
R213  4.7K_0201_5%  [R_0201]  21.14 46.75 180 bottom
R214  4.7K_0201_5%  [R_0201]  21.14 46.19 180 bottom
R215  4.7K_0201_5%  [R_0201]  17.07 41.68 270 bottom
R216  0.01_0603_1%  [R_0603]  99.47 84.19 270 top
R217  100K_0201_5%  [R_0201]  99.33 89.82 180 top
R218  0_0402_5%  [R_0402]  237.66 133.08 0 top
R219  0_0402_5%~D  [R0402_0OHM]  199.85 127.66 180 top
R220  100K_0201_5%  [R_0201]  191.22 100.11 90 top
R221  0.01_0603_1%  [R_0603]  190.1 105.51 90 top
R222  0.01_0603_1%  [R_0603]  193.27 105.51 90 top
R223  100K_0201_5%  [R_0201]  190.7 99.47 0 top
R224  0.01_0603_1%  [R_0603]  35.92 90.98 270 top
R225  100K_0201_5%  [R_0201]  34.14 96.29 270 top
R227  0.01_0603_1%  [R_0603]  27.79 67.5 0 top
R228  0_0402_5%~D  [R0402_0OHM]  33.13 87.47 270 top
R229  0.01_0603_1%  [R_0603]  28.14 64.42 0 top
R231  0_0402_5%~D  [R0402_0OHM]  140.4 129.55 0 top
R232  100K_0201_5%  [R_0201]  23.09 64.94 90 top
R234  0.01_0603_1%  [R_0603]  195.38 124.23 270 top
R238  100K_0201_5%  [R_0201]  33.57 96.27 270 top
R327  0.01_0603_1%  [R_0603]  102.57 84.19 270 top
R389  100K_0201_5%  [R_0201]  101.43 89.5 270 top
R391  10K_0201_5%  [R_0201]  230.78 108.52 90 top
R392  10K_0201_5%  [R_0201]  230.78 110.5 270 top
R395  10K_0201_5%  [R_0201]  230.19 108.52 90 top
R396  10K_0201_5%  [R_0201]  230.19 110.5 270 top
R398  0_0201_5%  [R_0201]  232.37 106.09 90 top
R399  0_0201_5%  [R0201_0OHM]  231.41 108.52 90 top
R400  0_0201_5%  [R0201_0OHM]  231.36 109.91 90 top
R514  0.01_0603_1%  [R_0603]  226.04 125.19 270 top
R515  0.01_0603_1%  [R_0603]  227.74 129.13 90 top
R716  3.3K_0402_1%  [R_0402]  228.85 142.54 0 top
R924  0_0402_5%~D  [R0402_0OHM]  30.89 7.15 0 top
R1012  0_0402_5%~D  [R_0402]  181.26 99.6 0 top
R1013  0_0402_5%~D  [R_0402]  181.26 100.62 0 top
R1014  10K_0201_5%  [R_0201]  184.05 105.04 180 top
R1015  0_0201_5%  [R0201_0OHM]  184.17 100.47 180 top
R1016  0_0201_5%  [R0201_0OHM]  184.14 99.45 180 top
R1017  0_0201_5%  [R0201_0OHM]  188.66 96.93 0 top
R1025  0_0402_5%~D  [R0402_0OHM]  157.66 94.01 180 top
R1027  0_0402_5%  [R_0402]  104.83 93.66 270 top
R1028  0_0402_5%~D  [R0402_0OHM]  99.85 93.85 270 top
R1029  0_0402_5%  [R_0402]  137.52 87.29 180 top
R1030  0_0402_5%  [R_0402]  136.64 84.64 0 top
R1032  220K_0201_5%  [R_0201]  195.35 101.38 180 top
R1033  33_0201_1%  [R_0201]  203.24 135.31 90 top
R1034  33_0201_1%  [R_0201]  204.51 133.8 180 top
R1035  0_0402_5%~D  [R0402_0OHM]  204.6 132.19 180 top
R1036  0_0402_5%~D  [R0402_0OHM]  204.6 133.07 180 top
R1037  2.2K_0201_5%  [R_0201]  233.67 123.78 180 bottom
R1038  0_0402_5%~D  [R0402_0OHM]  100.21 96.29 0 top
R1039  0_0402_5%~D  [R0402_0OHM]  102.88 96.29 180 top
R1040  100K_0201_5%  [R_0201]  231.76 118.49 90 top
R1041  100K_0201_5%  [R_0201]  228.67 130.08 0 top
R1043  0_0402_5%  [R_0402]  152.71 100.62 270 top
R1044  2.2K_0201_5%  [R_0201]  234.87 123.78 0 bottom
R1045  100K_0201_5%  [R_0201]  228.2 120.21 270 top
R1046  100K_0201_5%  [R_0201]  232.87 123.06 270 bottom
R1047  100K_0201_5%  [R_0201]  229.53 122.89 0 bottom
R1048  100K_0201_5%  [R_0201]  231.78 106.68 270 top
R1049  2.2K_0201_5%  [R_0201]  234.88 128.39 90 top
R1050  2.2K_0201_5%  [R_0201]  237.79 124.04 0 top
R1053  10K_0201_5%  [R_0201]  238.55 125.24 180 top
R1055  100K_0201_5%  [R_0201]  232.39 119.03 270 top
R1056  100K_0201_5%  [R_0201]  226.28 121.75 180 top
R1057  10K_0201_5%  [R_0201]  233.89 121.2 90 bottom
R1059  10K_0201_5%  [R_0201]  231.12 119.07 270 top
R1060  10K_0201_5%  [R_0201]  234.14 122.47 90 bottom
R1061  100K_0201_5%  [R_0201]  237.26 130.84 180 top
R1062  100K_0201_5%  [R_0201]  234.31 128.39 90 top
R1063  100K_0201_5%  [R_0201]  227.12 128.29 0 top
R1064  100K_0201_5%  [R_0201]  234.8 131.26 270 top
R1065  10K_0201_5%  [R_0201]  211.59 144.29 90 top
R1066  10K_0201_5%  [R_0201]  211.02 144.29 90 top
R1067  10K_0201_5%  [R_0201]  210.45 144.29 90 top
R1068  10K_0201_5%  [R_0201]  209.86 144.29 90 top
R1069  0_0402_5%  [R_0402]  135.75 86.39 90 top
R1070  0.01_0603_1%  [R_0603]  32.75 90.98 270 top
R1071  1K_0201_5%  [R_0201]  13.94 94.06 0 top
R1072  1K_0201_5%  [R_0201]  10.89 94.06 180 top
R1074  100K_0201_5%  [R_0201]  130.32 81.46 270 top
R1075  560K_0402_5%  [R_0402]  83.99 128.39 270 top
R1076  470K_0402_5%  [R_0402]  85.19 128.11 0 top
R1079  2.2K_0201_5%  [R_0201]  226.85 120.18 180 top
R1080  2.2K_0201_5%  [R_0201]  226.85 119.59 180 top
R1081  100K_0201_5%  [R_0201]  237.2 131.48 0 top
R1082  10K_0201_5%  [R_0201]  220.86 123.46 180 top
R1083  2.2K_0201_5%  [R_0201]  232.4 132.77 180 bottom
R1087  2.2K_0201_5%  [R_0201]  226.61 120.29 0 bottom
R1091  0_0402_5%~D  [R_0402]  106.41 127.97 90 top
R1092  0_0402_5%~D  [R_0402]  105.39 127.97 90 top
R1093  0_0402_5%~D  [R_0402]  143.78 127.92 90 top
R1094  0_0402_5%~D  [R_0402]  142.77 127.92 90 top
R1095  0_0402_5%~D  [R0402_0OHM]  194.85 100.36 0 top
R1096  0_0402_5%~D  [R0402_0OHM]  194.85 99.35 0 top
R1097  0_0402_5%~D  [R_0402]  239.62 121.51 0 top
R1098  0_0402_5%~D  [R_0402]  239.62 120.49 0 top
R1099  0_0402_5%~D  [R_0402]  17.05 98.53 90 top
R1100  0_0402_5%~D  [R_0402]  16.03 98.53 90 top
R1101  4.99K_0402_0.5%  [R_0402]  50.4 95.72 90 top
R1104  0_0402_5%~D  [R0402_0OHM]  245.92 139.7 90 top
R1106  0_0402_5%~D  [R_0402]  108.31 127.97 90 top
R1107  0_0402_5%~D  [R0402_0OHM]  217.2 139.23 0 top
R1109  0_0402_5%~D  [R_0402]  107.3 127.97 90 top
R1115  0_0402_5%~D  [R_0402]  104.5 127.97 90 top
R1116  0_0402_5%~D  [R_0402]  103.49 127.97 90 top
R1118  0_0402_5%~D  [R_0402]  158.3 134.27 180 top
R1121  0_0402_5%~D  [R_0402]  158.3 133.26 180 top
R1127  0_0402_5%~D  [R_0402]  145.68 127.91 90 top
R1128  0_0402_5%~D  [R_0402]  144.66 127.91 90 top
R1132  0_0402_5%~D  [R_0402]  158.3 132.37 180 top
R1133  0_0402_5%~D  [R_0402]  158.3 131.35 180 top
R1134  0_0402_5%~D  [R_0402]  158.3 136.18 180 top
R1135  0_0402_5%~D  [R_0402]  158.3 135.16 180 top
R1136  10K_0201_5%  [R_0201]  137.81 93.38 180 top
R1138  10K_0201_5%  [R_0201]  232.68 117.48 270 top
R1217  75_0402_5%  [R_0402]  227.64 115.48 180 top
R1224  100K_0201_5%  [R_0201]  101.87 98.22 180 bottom
R1225  100K_0201_5%  [R_0201]  154.59 100.26 180 bottom
R1377  10K_0402_5%~D  [R_0402]  207.88 107.69 180 top
R1378  10K_0402_5%~D  [R_0402]  208.77 108.57 90 top
R1379  10K_0201_5%  [R_0201]  31.61 42.94 270 top
R1380  10K_0201_5%  [R_0201]  32.18 42.94 270 top
R1381  10K_0201_5%  [R_0201]  33.33 42.7 270 top
R1382  10K_0201_5%  [R_0201]  33.91 43.06 270 top
R1383  3.3K_0201_1%  [R_0201]  35.85 27.35 90 top
R1384  3.3K_0201_1%  [R_0201]  35.29 27.35 90 top
R1385  3.3K_0201_1%  [R_0201]  34.72 27.35 90 top
R1386  3.3K_0201_1%  [R_0201]  35.86 38.28 0 top
R1387  4.75K_0402_0.5%  [R_0402]  24.4 28.41 270 top
R1388  10K_0201_1%  [R_0201]  32.23 31.11 0 top
R1389  2.2K_0201_5%  [R_0201]  30.83 28.53 270 top
R1390  2.2K_0201_5%  [R_0201]  30.26 28.53 270 top
R1391  2.2K_0201_5%  [R_0201]  30.35 34.58 0 bottom
R1392  499_0201_5%  [R_0201]  23.6 40.74 270 bottom
R1393  499_0201_5%  [R_0201]  22.71 40.74 270 bottom
R1394  2.2K_0201_5%  [R_0201]  30.66 33.38 90 bottom
R1395  2.2K_0201_5%  [R_0201]  29.37 33.71 0 bottom
R1396  2.2K_0201_5%  [R_0201]  25.52 31.15 270 bottom
R1397  2.2K_0201_5%  [R_0201]  27.55 28.57 270 top
R1398  2.2K_0201_5%  [R_0201]  26.98 28.57 270 top
R1399  10K_0201_1%  [R_0201]  28.95 28.66 270 top
R1400  10K_0201_1%  [R_0201]  29.53 28.66 270 top
R1401  10K_0201_1%  [R_0201]  20.85 30.79 270 bottom
R1402  10K_0201_1%  [R_0201]  22.47 28.52 270 top
R1403  1M_0201_1%  [R_0201]  31.4 28.53 270 top
R1404  10K_0201_1%  [R_0201]  24.09 28.42 270 bottom
R1405  1M_0201_1%  [R_0201]  23.06 28.52 270 top
R1406  10K_0201_1%  [R_0201]  21.69 30.73 270 bottom
R1407  10K_0201_1%  [R_0201]  22.7 30.77 270 bottom
R1408  100K_0201_5%  [R_0201]  28.04 27.3 180 top
R1409  100K_0201_5%  [R_0201]  22.97 28.52 270 bottom
R1410  0_0402_5%~D  [R0402_0OHM]  29.84 44.23 270 top
R1411  100K_0201_5%  [R_0201]  21.77 28.52 270 top
R1412  100K_0201_5%  [R_0201]  23.09 33.04 90 bottom
R1413  100K_0201_5%  [R_0201]  31.97 28.53 270 top
R1414  100K_0201_5%  [R_0201]  32.23 31.69 0 top
R1415  100K_0201_5%  [R_0201]  23.64 28.52 270 top
R1416  100K_0201_5%  [R_0201]  24.87 31.15 270 bottom
R1417  0_0402_5%~D  [R0402_0OHM]  30.85 44.23 270 top
R1418  1M_0201_1%  [R_0201]  18.32 31.22 180 top
R1419  1M_0201_1%  [R_0201]  20.67 32.28 180 bottom
R1420  1M_0201_1%  [R_0201]  20.67 31.71 180 bottom
R1421  1M_0201_1%  [R_0201]  18.4 31.92 180 top
R1422  0_0603_5%  [R_0603]  20.19 23.52 0 top
R1423  0_0603_5%  [R_0603]  22.42 24.72 180 top
R1424  0.01_1206_1%  [R_1206]  17.93 57.39 180 top
R1427  0_0603_5%  [R_0603]  26.75 57.37 270 top
R1428  0_0603_5%  [R_0603]  12.72 57.68 270 top
R1430  0_0402_5%~D  [R0402_0OHM]  11.64 46.16 0 top
R1431  0_0402_5%~D  [R0402_0OHM]  12.15 47.34 90 top
R1432  0_0402_5%~D  [R0402_0OHM]  7.83 58.66 180 top
R1434  0_0402_5%  [R_0402]  18.79 52.01 270 top
R1435  0_0402_5%~D  [R0402_0OHM]  10.79 46.16 180 top
R1436  0_0402_5%~D  [R0402_0OHM]  24.77 56.02 90 top
R1437  0_0402_5%~D  [R0402_0OHM]  29.41 53.9 0 top
R1438  0_0402_5%~D  [R0402_0OHM]  25.15 47.99 270 top
R1439  0_0402_5%  [R_0402]  29.41 52.12 0 top
R1440  0_0402_5%  [R_0402]  8.39 56.27 0 top
R1443  0_0201_5%  [R0201_0OHM]  9.1 47.79 90 top
R1444  0_0201_5%  [R0201_0OHM]  8.53 47.73 90 top
R1445  100K_0402_5%  [R_0402]  16.02 53.26 0 top
R1449  10K_0402_5%  [R_0402]  8.69 58.67 270 top
R1450  15K_0402_1%  [R_0402]  7.83 52.59 180 top
R1454  10K_0402_5%  [R_0402]  23.86 56.93 270 top
R1457  0_0402_5%~D  [R0402_0OHM]  28.47 45.79 180 top
R1458  0_0402_5%~D  [R0402_0OHM]  26.14 45.93 180 top
R1459  10K_0402_5%  [R_0402]  9.75 58.66 0 top
R1460  10K_0402_5%  [R_0402]  21.13 51.07 180 top
R1461  100K_0402_5%  [R_0402]  19.93 58.63 180 top
R1462  100K_0402_5%  [R_0402]  20.77 58.63 0 top
R1463  100K_0402_5%  [R_0402]  6.06 58.67 270 top
R1464  100K_0402_5%  [R_0402]  6.92 57.78 0 top
R1466  0_0201_5%  [R0201_0OHM]  22.57 46.95 0 top
R1467  0_0201_5%  [R0201_0OHM]  22.55 47.53 90 top
R1468  100K_0402_5%  [R_0402]  29.41 53.01 0 top
R1473  15K_0402_1%  [R_0402]  21.62 46.22 0 top
R1474  100K_0402_5%  [R_0402]  25.7 56.93 270 top
R1475  100K_0402_5%  [R_0402]  24.77 58.68 270 top
R1476  100K_0402_5%  [R_0402]  25.7 57.77 90 top
R1477  3.3K_0402_0.5%  [R_0402]  23.86 57.77 90 top
R1478  100K_0402_5%  [R_0402]  20.97 47.07 90 top
R1479  100K_0402_5%  [R_0402]  21.83 47.07 90 top
R1480  100K_0402_5%  [R_0402]  6.71 49.44 0 top
R1481  100K_0402_5%  [R_0402]  6.71 48.55 0 top
R1482  100K_0402_5%  [R_0402]  6.85 46.19 0 top
R1483  100K_0402_5%  [R_0402]  6.06 51.79 90 top
R1484  100K_0402_5%  [R_0402]  24.64 63.53 0 top
R1485  100K_0402_5%  [R_0402]  27.46 58.66 180 top
R5588  0_0402_5%  [R_0402]  227.26 131.5 90 top
R5669  0_0402_5%~D  [R0402_0OHM]  227.96 138.21 180 top
R5670  10K_0201_1%  [R_0201]  17.13 31.53 270 top
R5671  10K_0201_5%  [R_0201]  234.74 115.73 0 top
R5673  0_0603_5%  [R_0603]  15.73 33.24 90 top
R5674  0_0402_5%  [R_0402]  224.11 138.69 180 top
R5675  0_0402_5%  [R_0402]  224.11 137.8 180 top
R5676  10K_0201_5%  [R_0201]  209.29 144.29 90 top
R5677  10K_0201_5%  [R_0201]  208.71 144.29 90 top
R5678  0_0402_5%~D  [R0402_0OHM]  10.8 43.47 270 top
R5679  0_0402_5%~D  [R0402_0OHM]  9.91 43.47 270 top
R5680  0_0402_5%~D  [R0402_0OHM]  26.96 46.77 0 top
R5681  0_0402_5%~D  [R0402_0OHM]  26.96 47.66 0 top
R5682  0_0402_5%~D  [R0402_0OHM]  6.08 54.49 270 top
R5683  0_0402_5%  [R_0402]  20.22 51.98 0 top
R5684  0_0201_5%  [R_0201]  13.44 53.08 90 bottom
R5685  0_0201_5%  [R_0201]  12.85 53.75 180 bottom
R5686  0_0201_5%  [R_0201]  26.18 54.52 180 bottom
R5687  0_0201_5%  [R_0201]  24.75 54.52 180 bottom
R5688  0_0201_5%  [R_0201]  10.86 48.67 0 bottom
R5689  0_0201_5%  [R_0201]  10.86 50.2 0 bottom
R5690  0_0201_5%  [R_0201]  12.13 48.67 0 bottom
R5691  0_0201_5%  [R_0201]  12.13 50.2 0 bottom
R5692  0_0201_5%  [R_0201]  24.71 49.44 0 bottom
R5693  0_0201_5%  [R_0201]  26.27 47.95 270 bottom
R5694  0_0201_5%  [R_0201]  25.98 49.44 0 bottom
R5695  0_0201_5%  [R_0201]  27.16 47.37 90 bottom
R5696  10K_0201_1%  [R_0201]  20.26 29.48 180 bottom
R5698  0_0201_5%  [R_0201]  18.61 53.77 0 bottom
R5699  0_0201_5%  [R_0201]  20.61 52.86 90 bottom
R5700  0_0201_5%  [R_0201]  7.73 51.51 270 bottom
R5701  0_0201_5%  [R_0201]  21.77 52.86 90 bottom
R5702  0_0402_5%  [R_0402]  229.42 116.12 180 top
R5703  100K_0201_5%  [R_0201]  128.32 82.16 180 top
R5704  100K_0201_5%  [R_0201]  126.61 82.82 90 top
R5705  0.01_0603_1%  [R_0603]  183.47 103.35 270 top
R5706  0_0201_5%  [R_0201]  39.02 38.29 90 top
R5707  0_0201_5%  [R_0201]  33.42 28.79 180 top
R5708  0_0201_5%  [R_0201]  32.23 29.96 0 top
R5709  0_0201_5%  [R_0201]  37.46 38.24 90 top
R5711  100K_0201_5%  [R_0201]  202.28 147.16 90 top
R5712  0_0402_5%~D  [R0402_0OHM]  202.41 145.54 0 top
R5713  0_0402_5%~D  [R0402_0OHM]  195.43 133.31 90 top
R5714  0_0402_5%  [R_0402]  198.53 129.26 0 top
R5715  10K_0402_5%  [R_0402]  201.02 138.04 270 top
R5716  10K_0402_5%  [R_0402]  200.22 148.32 0 top
R5717  0.01_0603_1%  [R_0603]  195.18 135.1 90 top
R5718  0.01_0603_1%  [R_0603]  204.2 134.59 90 top
R5719  100K_0201_5%  [R_0201]  226.75 135.68 180 top
R5720  0_0201_5%  [R0201_0OHM]  10.88 47.77 90 top
R5721  0_0201_5%  [R0201_0OHM]  10.27 47.77 90 top
R5722  0_0201_5%  [R_0201]  10.86 47.13 180 top
R5723  0_0201_5%  [R_0201]  9.68 47.77 90 top
R5724  0_0201_5%  [R0201_0OHM]  24.43 47.54 90 top
R5725  0_0201_5%  [R0201_0OHM]  23.76 46.95 0 top
R5726  0_0201_5%  [R_0201]  23.85 47.54 90 top
R5727  0_0201_5%  [R_0201]  23.27 47.54 90 top
R5728  100K_0201_5%  [R_0201]  94.3 102.5 180 top
R5729  0.01_0603_1%  [R_0603]  93.64 99.58 0 top
R5730  0_0201_5%  [R_0201]  21.2 52.86 90 bottom
R5731  0_0201_5%  [R_0201]  18.61 54.34 0 bottom
R5732  100K_0201_5%  [R_0201]  225.08 122.99 0 top
R5734  0_0201_5%  [R_0201]  23.94 63.02 90 top
R5736  0_0201_5%  [R_0201]  26.38 63.06 90 top
R5738  100K_0201_5%  [R_0201]  227.7 125.36 180 top
R5739  100_0402_5%  [R_0402]  203.31 140.15 180 top
R5741  0_0201_5%  [R0201_0OHM]  27.6 63.51 180 top
R5742  1M_0402_5%  [R_0402]  6.93 55.11 0 top
R5743  0_0402_5%  [R_0402]  227.2 121.75 0 top
R5745  0_0402_5%~D  [R_0402]  21 22.46 180 top
R5746  100K_0402_5%~D  [R_0402]  219.23 115.65 0 top
R5750  0_0201_5%  [R_0201]  221.84 118.88 0 top
R5751  0_0201_5%  [R_0201]  217.95 118.85 0 top
R5752  0_0201_5%  [R_0201]  218.46 115.78 180 top
R5753  0_0201_5%  [R0201_0OHM]  155.04 96.96 180 top
R5754  100K_0201_5%  [R_0201]  38.56 96.41 270 top
R5755  100K_0201_5%  [R_0201]  22.52 65.46 90 top
R5756  10K_0201_1%  [R_0201]  23.06 27.34 0 top
R5757  10K_0201_5%  [R_0201]  164.13 94.56 270 top
R5758  0_0402_5%  [R_0402]  227.64 144.06 0 top
R5759  0_0201_5%  [R_0201]  12.82 53.12 180 bottom
R5760  0_0201_5%  [R_0201]  25.84 52.83 180 bottom
R5761  0_0402_5%  [R_0402]  241.57 114.79 180 top
R5762  0_0402_5%  [R_0402]  241.57 115.67 180 top
RA1  7.5_0402_1%  [R_0402]  28.51 10.83 180 top
RA2  7.5_0402_1%  [R_0402]  28.51 11.72 180 top
RA3  1K_0402_5%  [R_0402]  25 11.77 90 top
RA4  1K_0402_5%  [R_0402]  25 10.78 270 top
RA5  2.2K_0402_5%  [R_0402]  21.06 13.95 270 top
RA6  0_0402_5%  [R_0402]  21.94 14.55 90 top
RA7  2.2K_0402_5%  [R_0402]  20.17 13.95 270 top
RA13  100K_0201_5%  [R_0201]  18.14 16 270 top
RA14  33_0201_1%  [R_0201]  23.44 22.77 0 top
RA15  100K_0201_5%  [R_0201]  16.87 16 270 top
RA17  1K_0201_5%  [R_0201]  17.51 16 270 top
RA18  47K_0402_5%  [R_0402]  20.1 19.34 0 top
RA19  100K_0201_5%  [R_0201]  18.74 15.5 0 top
RA21  47K_0402_5%  [R_0402]  20.1 20.23 0 top
RA23  100K_0201_1%  [R_0201]  25.04 26.07 180 top
RA24  200K _0201_1%  [R_0201]  23.22 24.63 90 top
RA25  100K_0201_1%  [R_0201]  36.43 24.58 270 top
RA26  10K_0201_5%  [R_0201]  30.88 22.64 180 bottom
RA27  0.01_0603_1%  [R_0603]  20.61 21.31 0 top
RA28  10K_0201_5%  [R_0201]  30.3 22 0 bottom
RA30  1K_0402_5%~D  [R_0402]  32.48 11.59 0 top
RA31  1K_0402_5%~D  [R_0402]  32.48 10.32 0 top
RA32  4.7K_0402_5%  [R_0402]  34.4 12.68 270 top
RA33  4.7K_0402_5%  [R_0402]  34.4 9.99 90 top
RA49  0_0402_5%~D  [R0402_0OHM]  33.76 25.46 270 top
RA50  0_0402_5%~D  [R0402_0OHM]  32.72 25.27 270 top
RA51  0_0402_5%~D  [R0402_0OHM]  23.98 24.34 90 top
RA52  0_0402_5%~D  [R0402_0OHM]  35.59 25.27 180 top
RA53  0_0402_5%~D  [R0402_0OHM]  35.65 24.24 180 top
RA54  0_0402_5%~D  [R0402_0OHM]  30.86 25.37 270 top
RA55  0_0402_5%~D  [R0402_0OHM]  28.78 25.58 270 top
RA56  0_0402_5%~D  [R0402_0OHM]  31.85 25.27 270 top
RA57  0_0402_5%~D  [R0402_0OHM]  29.87 25.39 270 top
RA60  0_0402_5%~D  [R0402_0OHM]  32.34 26.73 0 top
RA61  0_0402_5%~D  [R0402_0OHM]  29.44 12.73 0 top
RA62  10K_0201_5%  [R_0201]  200.17 123.22 180 top
RA63  0_0402_5%~D  [R0402_0OHM]  28.56 13.5 270 top
RA64  10K_0201_5%  [R_0201]  200.17 124.75 180 top
RA65  0_0402_5%~D  [R0402_0OHM]  207.05 127.36 270 top
RA66  0_0402_5%~D  [R0402_0OHM]  204.37 126.53 0 top
RA67  10K_0201_5%  [R_0201]  204.32 115.44 90 top
RA68  0.1_0805_1%  [R_0805]  239.9 135.61 0 top
RA69  0.1_0805_1%  [R_0805]  29.24 92.59 180 top
RA70  1K_0201_5%  [R_0201]  208.1 127.29 0 top
RA71  1K_0201_5%  [R_0201]  209.95 127.29 180 top
RA72  1K_0402_1%  [R_0402]  37.18 24.16 0 top
RA73  BLM15PX181SN1D_2P  [MURAT_BLM15PX181SN1D_2P]  241.95 134.2 0 top
RA74  BLM15PX181SN1D_2P  [MURAT_BLM15PX181SN1D_2P]  241.61 137.03 0 top
RA75  BLM15PX181SN1D_2P  [MURAT_BLM15PX181SN1D_2P]  26.01 93.42 180 top
RA76  BLM15PX181SN1D_2P  [MURAT_BLM15PX181SN1D_2P]  26.01 92.31 180 top
RA77  0_0201_5%  [R_0201]  23.44 23.53 0 top
RA78  0_0402_5%~D  [R_0402]  207.26 128.3 180 top
RA79  0_0402_5%~D  [R_0402]  209.71 126.53 0 top
RC2  0_0201_5%  [R_0201]  124.73 95.41 180 top
RC3  100K_0201_5%  [R_0201]  139.72 94.52 180 top
RC4  24.9_0402_1%  [R_0402]  121.77 95.36 270 top
RC5  0_0201_5%  [R_0201]  121.39 88.59 270 top
RC6  2.2K_0201_5%  [R_0201]  136.79 99.06 180 bottom
RC7  10K_0201_5%  [R_0201]  141.37 112.17 180 bottom
RC8  499_0402_1%  [R_0402]  121.01 92.67 90 top
RC9  1K_0402_5%  [R_0402]  137.38 89.68 0 top
RC10  10K_0201_5%  [R_0201]  137.52 98.24 270 bottom
RC11  0_0402_5%  [R_0402]  112.96 96.55 180 top
RC12  0_0201_5%  [R_0201]  114.13 89.95 0 top
RC13  1K_0402_5%  [R_0402]  120.12 93.58 270 top
RC14  49.9_0201_1%  [R_0201]  137.39 115.31 90 top
RC15  49.9_0201_1%  [R_0201]  138.03 115.1 90 top
RC16  2.2K_0201_5%  [R_0201]  136.8 98.33 180 bottom
RC18  51_0402_5%  [R_0402]  121.22 89.31 180 top
RC19  51_0402_5%  [R_0402]  108.97 92.67 90 top
RC20  51_0402_5%  [R_0402]  128.68 92.69 180 top
RC22  0_0201_5%  [R_0201]  121.52 95.07 270 bottom
RC23  51_0402_5%  [R_0402]  125.51 94.5 90 top
RC24  51_0402_5%  [R_0402]  113.34 89.95 180 top
RC25  51_0402_5%  [R_0402]  125.72 89.66 180 top
RC26  1K_0402_5%  [R_0402]  127.31 85.56 180 top
RC27  0_0201_5%  [R_0201]  124.73 94.78 180 top
RC28  1K_0402_5%  [R_0402]  112.55 88.25 0 top
RC29  1K_0402_5%  [R_0402]  123.76 92.74 180 top
RC31  1K_0402_1%  [R_0402]  107.83 93.58 270 top
RC32  2.2K_0201_5%  [R_0201]  141.71 95.63 90 bottom
RC33  2.2K_0201_5%  [R_0201]  142.35 95.63 90 bottom
RC34  51_0402_5%  [R_0402]  125.72 88.77 180 top
RC35  51_0402_5%  [R_0402]  119.74 95.41 270 top
RC36  1K_0402_5%  [R_0402]  118.22 89.01 270 top
RC37  51_0402_5%  [R_0402]  129.72 93.57 180 top
RC38  51_0402_5%  [R_0402]  122.12 88.49 90 top
RC39  0_0402_5%  [R_0402]  113.62 93.75 90 top
RC40  1K_0402_5%  [R_0402]  112.73 93.75 90 top
RC41  51_0402_5%  [R_0402]  122.87 95.13 270 top
RC42  1K_0402_5%  [R_0402]  119.23 93.58 270 top
RC43  0_0201_5%  [R_0201]  126.44 89.81 0 top
RC44  0_0201_5%  [R_0201]  129.38 92.74 0 top
RC45  200_0201_1%  [R_0201]  114.07 108.75 180 top
RC46  80.6_0201_1%  [R_0201]  114.07 110.14 180 top
RC47  162_0201_1%  [R_0201]  114.07 107.98 180 top
RC48  0_0402_5%  [R_0402]  106.94 93.58 270 top
RC49  0_0201_5%  [R_0201]  119.54 88.6 270 top
RC50  10K_0201_5%  [R_0201]  138.28 95.5 90 bottom
RC51  0_0201_5%  [R_0201]  126.44 89.25 0 top
RC52  0_0201_5%  [R_0201]  130.46 94.34 270 top
RC53  0_0402_5%  [R_0402]  206.31 135.52 0 top
RC54  0_0402_5%  [R_0402]  213.04 138.01 90 top
RC55  0_0402_5%  [R_0402]  210.8 138.01 90 top
RC56  0_0402_5%  [R_0402]  209.78 138.01 90 top
RC57  0_0402_5%  [R_0402]  208.77 138.01 90 top
RC58  0_0402_5%  [R_0402]  207.75 138.01 90 top
RC59  0_0402_5%  [R_0402]  204.32 138.92 270 top
RC60  200_0402_1%  [R_0402]  140.14 111.04 180 top
RC61  200_0402_1%  [R_0402]  138.61 109.57 180 top
RC62  0_0201_5%  [R_0201]  115.98 89.95 180 top
RC63  0_0201_5%  [R_0201]  123.58 94.71 270 top
RC64  100_0201_1%  [R_0201]  130.64 95.51 0 top
RC65  0_0201_5%  [R_0201]  111.49 93.29 270 top
RC66  0_0201_5%  [R_0201]  123.34 93.51 180 top
RC67  0_0201_5%  [R_0201]  139.69 89.69 180 top
RC68  0_0201_5%  [R_0201]  110.93 93.29 270 top
RC69  0_0201_5%  [R_0201]  118.1 83.35 90 bottom
RC70  0_0201_5%  [R_0201]  117.47 83.35 90 bottom
RC71  0_0402_5%~D  [R0402_0OHM]  164.8 103.28 90 top
RC72  0_0402_5%~D  [R0402_0OHM]  163.53 109.76 270 top
RC73  15_0402_1%  [R_0402]  149.93 94.14 180 top
RC75  15_0402_1%  [R_0402]  149.93 95.03 180 top
RC76  15_0402_1%  [R_0402]  149.93 96.81 180 top
RC77  15_0402_1%  [R_0402]  149.93 95.92 180 top
RC79  60.4_0402_1%  [R_0402]  112.05 95.54 0 top
RC80  15_0402_1%  [R_0402]  155.75 96.82 0 top
RC81  1K_0201_5%  [R_0201]  146.51 100.83 90 top
RC82  1K_0201_5%  [R_0201]  145.9 100.83 90 top
RC83  100K_0201_5%  [R_0201]  139.34 108.24 180 bottom
RC84  150K_0402_5%  [R_0402]  142.22 108.99 90 top
RC85  150K_0402_5%  [R_0402]  141.23 113.22 180 top
RC86  4.7K_0201_5%  [R_0201]  138.32 100.87 180 bottom
RC87  113_0402_1%  [R_0402]  138.78 100.58 0 top
RC88  100_0201_1%  [R_0201]  131.82 95.51 0 top
RC89  15_0402_1%  [R_0402]  163.18 91.65 90 top
RC90  10K_0201_5%  [R_0201]  137.78 110.31 270 bottom
RC91  1K_0201_5%  [R_0201]  140.4 101.57 0 top
RC97  100_0201_1%  [R_0201]  129.69 108.11 180 bottom
RC98  100_0201_1%  [R_0201]  130.5 108.24 0 bottom
RC102  0_0402_5%  [R_0402]  132.95 93.05 180 top
RC106  0_0402_5%~D  [R0402_0OHM]  129.71 94.45 90 top
RC128  0.01_0603_1%  [R_0603]  141.19 112.3 270 top
RC136  1K_0201_5%  [R_0201]  135.55 104.38 270 bottom
RC139  100_0201_1%  [R_0201]  117.21 100.54 180 bottom
RC140  0_0402_5%~D  [R0402_0OHM]  128.82 95.36 270 top
RC141  100_0201_1%  [R_0201]  115.26 100.87 0 bottom
RC142  56_0201_5%  [R_0201]  116.97 92.54 0 top
RC143  220_0402_5%  [R_0402]  116.57 94.22 270 top
